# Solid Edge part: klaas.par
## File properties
Author: Cymax
Template: Normal.par
Last saved by: Cymax
Revision: 17
Application: Solid Edge
Material: Glass, general industrial
Face Style: White (glass)
Fill Style: ANSI36(Marble)
Virtual Style: White (Glass)
Coef. of Thermal Exp: 0.0
Thermal Conductivity: 0.0
Specific Heat: 0.0
Modulus of Elasticity: 0.0
Poission's Ratio: 0.0
Yield Stress: 0.0
Ultimate Stress: 0.0
Elongation: 0.0
Density: 2595,000 kg/m^3
Accuracy: 0,990
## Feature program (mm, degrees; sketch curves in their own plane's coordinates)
sketch for "unnamed RevolvedProtrusion 1" #1 plane through (0, -682.1712, -217.5478) normal (0, -0.984808, -0.173648) x-axis (-1, 0, 0)
sketch for "unnamed RevolvedProtrusion 1" #2 plane through (0, -682.1712, -217.5478) normal (0, -0.984808, -0.173648) x-axis (-1, 0, 0)
revolve "unnamed RevolvedProtrusion 1" add finite
sketch used by "unnamed Protrusion 1" plane through (1190.304, -586.8599, -182.2082) normal (0, -0.984808, -0.173648) x-axis (-1, 0, 0)
  line (-266.3513, 164.7232) -> (954.7049, 164.7232)
extrude "unnamed Protrusion 1" add to key point along -normal
thinwall "Thinwall_10"  Thickness = 20 mm
sketch for "ExtrudedCutout_14" plane through (846.1272, -587.8978, 8.0446) normal (0, -0.173648, 0.984808) x-axis (1, 0, 0)
extrude "ExtrudedCutout_14" cut finite 1146.8285 along -normal
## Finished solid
Body 1: solid body, 39 faces, 96 edges, 64 vertices.
  Faces by surface: plane 23, cylinder 8, torus 8
  Edges by curve: line 56, circle 28, intersection 12
Bounding box of the edges (mm; curved faces can reach further): 1221.056 x 180.674 x 352.473, from (235.5991, -707.4018, -344.4289) to (1456.6554, -526.7275, 8.0446).
Cylindrical faces by radius (mm): R430.6294 x1, R437.3201 x1, R450.6294 x1, R457.3201 x1, R658.028 x2, R678.028 x2
Toroidal faces (ring radius, tube radius in mm): R478.028 r180 x4, R478.028 r200 x4
Planar faces by outward normal: +x 6, -x 6, oblique 11
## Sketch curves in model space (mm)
line (235.5991, -558.256, -344.4289) -> (235.5991, -619.4263, 2.4852)
line (235.5991, -619.4263, 2.4852) -> (1456.6554, -619.4263, 2.4852)
line (1456.6554, -619.4263, 2.4852) -> (1456.6554, -558.256, -344.4289)
line (1456.6554, -558.256, -344.4289) -> (235.5991, -558.256, -344.4289)
line (1415.304, -782.1798, 349.6287) -> (265.304, -782.1798, 349.6287)
arc centre (1165.304, -699.1711, -121.1371) radius 200 from (1165.304, -664.4414, -318.0986) through (1019.8293, -675.3381, -256.3003) to (965.304, -699.1711, -121.1371)
line (965.304, -699.1711, -121.1371) -> (965.304, -706.2399, -81.0475)
line (965.304, -706.2399, -81.0475) -> (1415.304, -706.2399, -81.0475)
line (1415.304, -706.2399, -81.0475) -> (1415.304, -699.1711, -121.1371)
arc centre (1215.304, -699.1711, -121.1371) radius 200 from (1215.304, -664.4414, -318.0986) through (1360.7788, -675.3381, -256.3003) to (1415.304, -699.1711, -121.1371)
line (1215.304, -664.4414, -318.0986) -> (1165.304, -664.4414, -318.0986)
line (265.304, -707.4018, -74.4585) -> (715.304, -707.4018, -74.4585)
line (715.304, -707.4018, -74.4585) -> (715.304, -699.1711, -121.1371)
arc centre (515.304, -699.1711, -121.1371) radius 200 from (715.304, -699.1711, -121.1371) through (652.5524, -673.9096, -264.4017) to (515.304, -664.4414, -318.0986)
line (515.304, -664.4414, -318.0986) -> (465.304, -664.4414, -318.0986)
arc centre (465.304, -699.1711, -121.1371) radius 200 from (265.304, -699.1711, -121.1371) through (328.0557, -673.9096, -264.4017) to (465.304, -664.4414, -318.0986)
line (265.304, -699.1711, -121.1371) -> (265.304, -707.4018, -74.4585)
circle centre (-1600, 600, 0) radius 75
line (0, 720.5308, 0) -> (0, 720.5308, -404.4594)
arc centre (0, 0, 1288.5152) radius 1839.926 from (0, -720.5308, -404.4594) through (0, 0, -551.4108) to (0, 720.5308, -404.4594)
line (0, -720.5308, -404.4594) -> (0, -720.5308, 0)
line (0, -720.5308, 0) -> (0, 720.5308, 0)
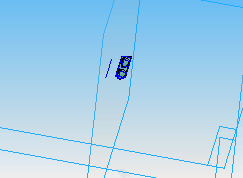
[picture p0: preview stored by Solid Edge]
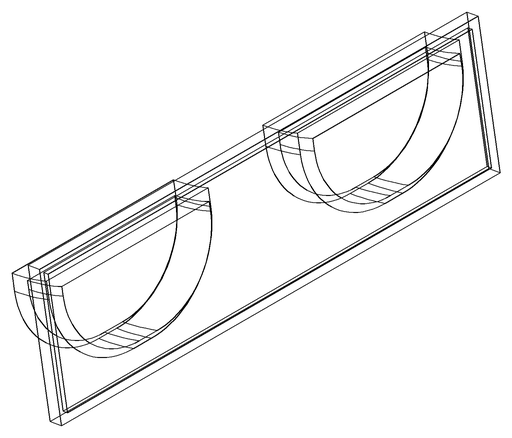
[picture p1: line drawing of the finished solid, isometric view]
